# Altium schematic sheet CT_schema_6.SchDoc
size 479 x 328 mm
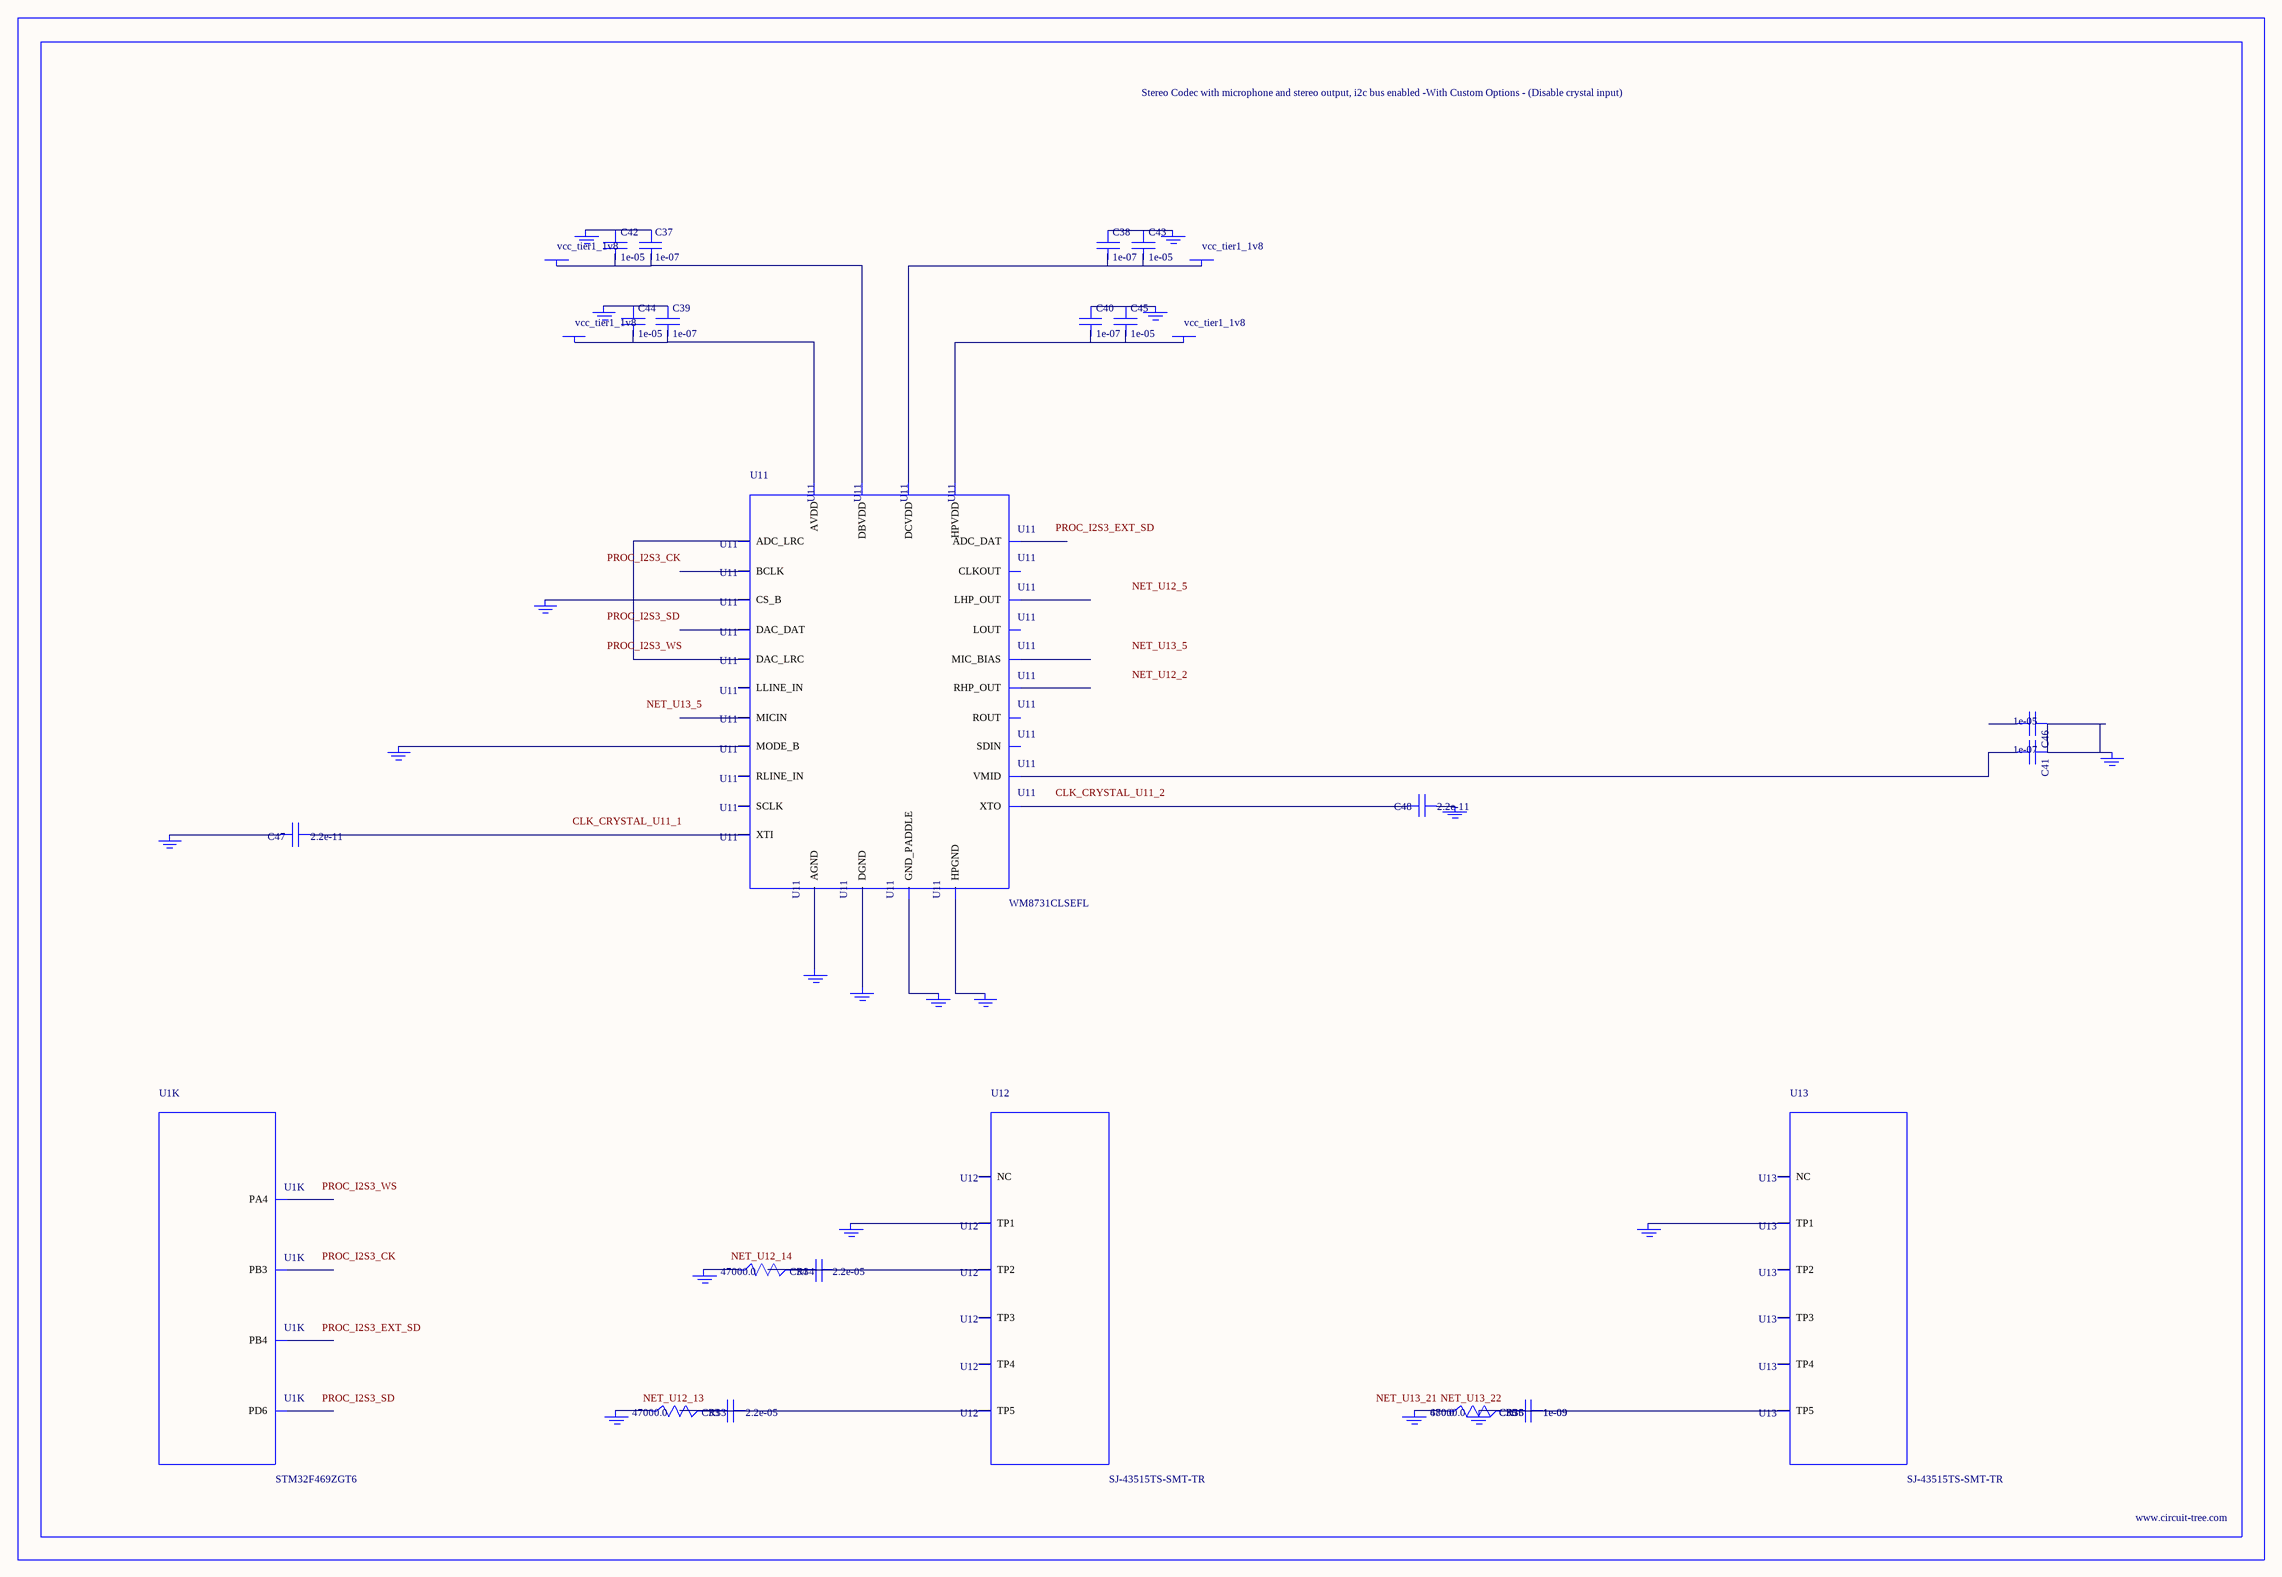
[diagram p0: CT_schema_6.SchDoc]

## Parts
BORDER5  (no value)
C33  2.2e-05  [C1210]
C34  2.2e-05  [C1210]
C35  1e-09  [C0402]
C36  1e-09  [C0402]
C37  1e-07  [C0402]
C38  1e-07  [C0402]
C39  1e-07  [C0402]
C40  1e-07  [C0402]
C41  1e-07  [C0402]
C42  1e-05  [C0805]
C43  1e-05  [C0805]
C44  1e-05  [C0805]
C45  1e-05  [C0805]
C46  1e-05  [C0805]
C47  2.2e-11  [C0402]
C48  2.2e-11  [C0402]
GND_INSTANCE_5_0  (no value)
GND_INSTANCE_5_1  (no value)
GND_INSTANCE_5_2  (no value)
GND_INSTANCE_5_3  (no value)
GND_INSTANCE_5_4  (no value)
GND_INSTANCE_5_5  (no value)
GND_INSTANCE_5_6  (no value)
GND_INSTANCE_5_7  (no value)
GND_INSTANCE_5_8  (no value)
GND_INSTANCE_5_9  (no value)
GND_INSTANCE_5_10  (no value)
GND_INSTANCE_5_11  (no value)
GND_INSTANCE_5_12  (no value)
GND_INSTANCE_5_13  (no value)
GND_INSTANCE_5_14  (no value)
GND_INSTANCE_5_15  (no value)
GND_INSTANCE_5_16  (no value)
GND_INSTANCE_5_17  (no value)
GND_INSTANCE_5_18  (no value)
POWER_INSTANCE_5_0  vcc_tier1_1v8
POWER_INSTANCE_5_1  vcc_tier1_1v8
POWER_INSTANCE_5_2  vcc_tier1_1v8
POWER_INSTANCE_5_3  vcc_tier1_1v8
R33  47000.0  [R0603]
R34  47000.0  [R0603]
R35  47000.0  [R0603]
R36  680.0  [R0603]
U1  STM32F469ZGT6  [LQFP144]  (part K of 12)
U11  WM8731CLSEFL  [QFN-28]
U12  SJ-43515TS-SMT-TR  [SJ-43515TS-SMT-TR]
U13  SJ-43515TS-SMT-TR  [SJ-43515TS-SMT-TR]

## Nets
NetC33_1: C33.1 C33.2 R33.2 U12.5(TP5)
NetC34_1: C34.1 C34.2 R34.2 U12.2(TP2)
NetC35_1: C35.1 C35.2 C36.1 C36.2 GND_INSTANCE_5_18.0(GND) R35.2 R36.2 U13.5(TP5)
NetC37_1: C37.1 C42.1 GND_INSTANCE_5_3.0(GND)
NetC37_2: C37.2 C42.2 POWER_INSTANCE_5_1.0(PWR) U11.5(DBVDD)
NetC38_1: C38.1 C43.1 GND_INSTANCE_5_2.0(GND)
NetC38_2: C38.2 C43.2 POWER_INSTANCE_5_0.0(PWR) U11.3(DCVDD)
NetC39_1: C39.1 C44.1 GND_INSTANCE_5_6.0(GND)
NetC39_2: C39.2 C44.2 POWER_INSTANCE_5_3.0(PWR) U11.18(AVDD)
NetC40_1: C40.1 C45.1 GND_INSTANCE_5_4.0(GND)
NetC40_2: C40.2 C45.2 POWER_INSTANCE_5_2.0(PWR) U11.12(HPVDD)
NetC41_1: C41.1 C46.1 GND_INSTANCE_5_7.0(GND)
NetC41_2: C41.2 U11.20(VMID)
NetC47_1: C47.1 U11.1(XTI)
NetC47_2: C47.2 GND_INSTANCE_5_0.0(GND)
NetC48_1: C48.1 GND_INSTANCE_5_1.0(GND)
NetC48_2: C48.2 U11.2(XTO)
NetGND_INSTANCE_5_5_0: GND_INSTANCE_5_5.0(GND) U11.15(HPGND)
NetGND_INSTANCE_5_8_0: GND_INSTANCE_5_8.0(GND) U11.25(MODE_B)
NetGND_INSTANCE_5_9_0: GND_INSTANCE_5_9.0(GND) U11.26(CS_B)
NetGND_INSTANCE_5_10_0: GND_INSTANCE_5_10.0(GND) U11.29(GND_PADDLE)
NetGND_INSTANCE_5_11_0: GND_INSTANCE_5_11.0(GND) U11.4(DGND)
NetGND_INSTANCE_5_12_0: GND_INSTANCE_5_12.0(GND) U11.19(AGND)
NetGND_INSTANCE_5_13_0: GND_INSTANCE_5_13.0(GND) U12.1(TP1)
NetGND_INSTANCE_5_14_0: GND_INSTANCE_5_14.0(GND) R34.1
NetGND_INSTANCE_5_15_0: GND_INSTANCE_5_15.0(GND) R33.1
NetGND_INSTANCE_5_16_0: GND_INSTANCE_5_16.0(GND) U13.1(TP1)
NetGND_INSTANCE_5_17_0: GND_INSTANCE_5_17.0(GND) R35.1 R36.1
NetU11_9: U11.9(DAC_LRC) U11.11(ADC_LRC)

Not connected (* = marked no-connect by the designer): C46 2; U1 35(PA4) 124(PD6) 132(PB3) 133(PB4); U11 6(CLKOUT) 7(BCLK) 8(DAC_DAT) 10(ADC_DAT) 13(LHP_OUT) 14(RHP_OUT) 16(LOUT) 17(ROUT) 21(MIC_BIAS) 22(MICIN) 23(RLINE_IN) 24(LLINE_IN) 27(SDIN) 28(SCLK); U12 3(TP3) 4(TP4) 6(NC); U13 2(TP2) 3(TP3) 4(TP4) 6(NC)

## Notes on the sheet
- Labels drawn without touching a wire or pin: CLK_CRYSTAL_U11_1, CLK_CRYSTAL_U11_2, NET_U12_2, NET_U12_5, NET_U12_13, NET_U12_14, NET_U13_5, NET_U13_21, NET_U13_22, PROC_I2S3_CK, PROC_I2S3_EXT_SD, PROC_I2S3_SD, PROC_I2S3_WS

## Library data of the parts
BORDER5 = BORDER_PAGE5
C33 C34 = C1210C224K5RACTU
C35 C36 = C0402C102K3RAC
C37-C41 = C0402C104K3RACTU
C42-C46 = C0805C106K8RACTU
C47 C48 = C0402C220K3RAC
GND_INSTANCE_5_0-GND_INSTANCE_5_18 = GND
POWER_INSTANCE_5_0-POWER_INSTANCE_5_3 = PWR
R33-R35 = RC0603JR-0747KL
R36 = RC0603JR-07680RL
